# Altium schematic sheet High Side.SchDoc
size 431 x 279 mm; Date: Not shown in title block; ApprovedBy: Not shown in title block; CheckedBy: Not shown in title block; Author: Not shown in title block; CompanyName: Not shown in title block; Engineer: Not shown in title block; Organization: Not shown in title block; Address1: Not shown in title block; Address2: Not shown in title block; Address3: Not shown in title block; Address4: Not shown in title block; DocumentNumber: 4; Revision: Use project parameter SCH_Rev; SheetNumber: 4; SheetTotal: 5; PageSetup: Record=PageOptions¦CenterHorizontal=True¦CenterVertical=True¦PrintScale=1.00¦XCorrection=1.00¦YCorrection=1.00¦PrintKind=0¦BorderSize=5000000¦LeftOffset=0¦BottomOffset=0¦Orientation=2¦PaperLength=1000¦PaperWidth=1000¦Scale=100¦PaperSource=15¦PrintQuality=600¦MediaType=1¦DitherType=10¦PaperKind=Letter¦PrintScaleMode=1
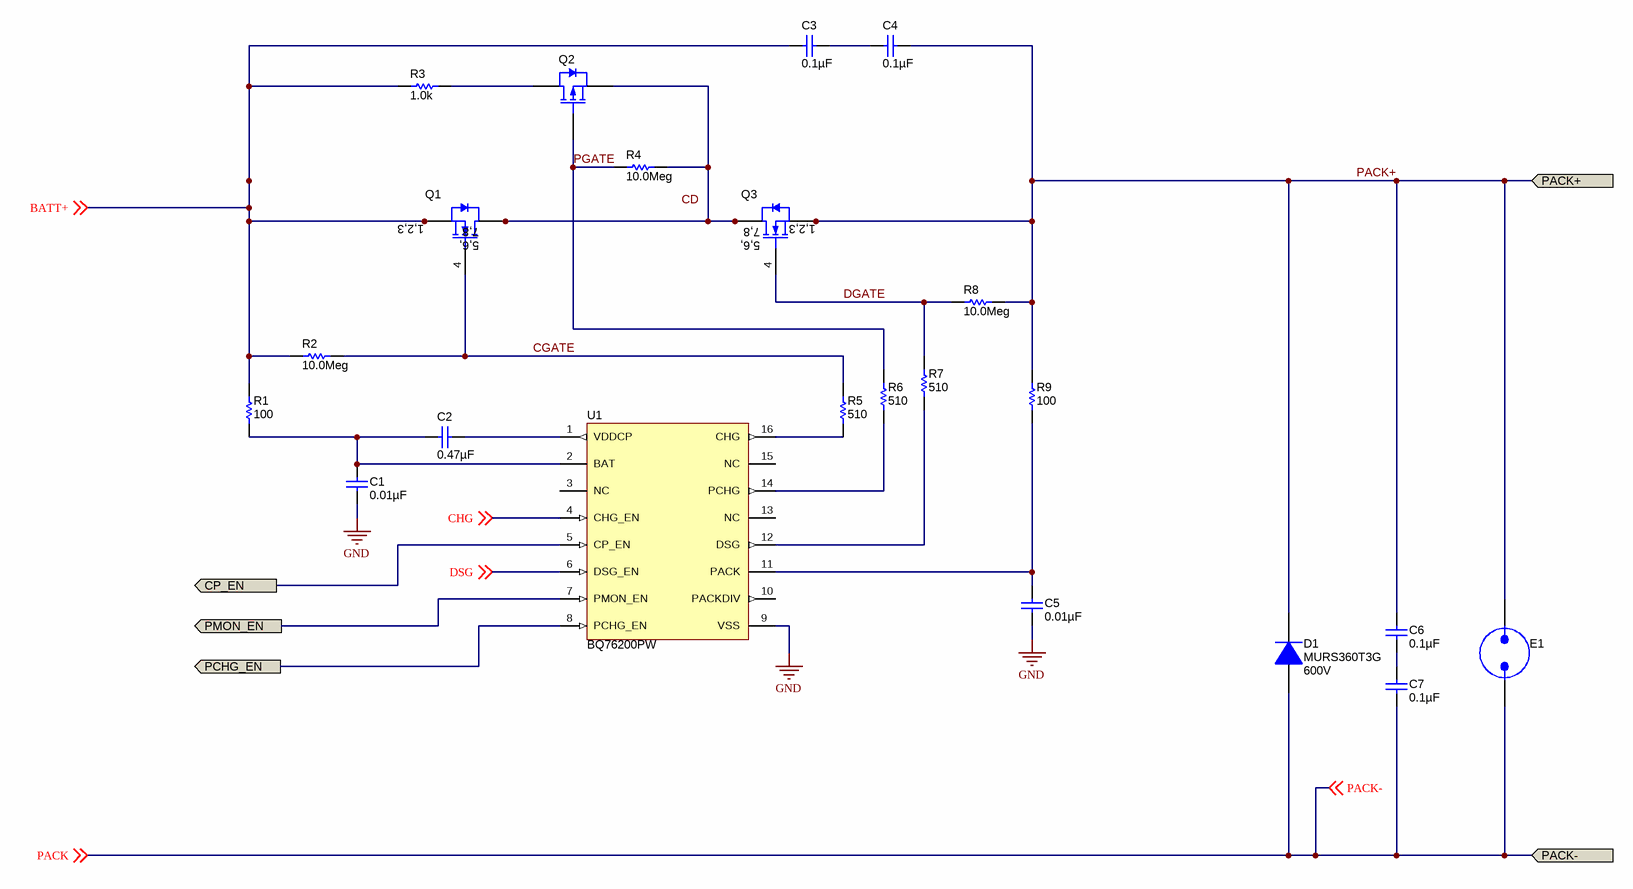
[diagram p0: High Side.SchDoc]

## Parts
C1  ValueDisplayed: 0.01µF  [0805_HV]  (hidden comment: 08051C103KAT2A)
C2  ValueDisplayed: 0.47µF  [0805_HV]  (hidden comment: C2012X7R1E474K)
C3  ValueDisplayed: 0.1µF  [0603]  (hidden comment: GRM188R72A104KA35D)
C4  ValueDisplayed: 0.1µF  [0603]  (hidden comment: GRM188R72A104KA35D)
C5  ValueDisplayed: 0.01µF  [0805_HV]  (hidden comment: 08051C103KAT2A)
C6  ValueDisplayed: 0.1µF  [0603]  (hidden comment: GRM188R72A104KA35D)
C7  ValueDisplayed: 0.1µF  [0603]  (hidden comment: GRM188R72A104KA35D)
D1  MURS360T3G  value 600V  [SMC]
E1  N/A  [SPARK_GAP2]  (value not drawn)  (no BOM)
Q1  CSD19531Q5A  [TRANS_NexFET_Q5A]  (value not drawn)
Q2  ZXMP10A13FTA  [SOT-23]  (value not drawn)
Q3  CSD19531Q5A  [TRANS_NexFET_Q5A]  (value not drawn)
R1  value 100  [0603]  (hidden comment: CRCW0603100RFKEA)
R2  value 10.0Meg  [0603]  (hidden comment: CRCW060310M0FKEA)
R3  value 1.0k  [2512M]  (hidden comment: ERJ-1TYJ102U)
R4  value 10.0Meg  [0603]  (hidden comment: CRCW060310M0FKEA)
R5  ValueDisplayed: 510  [0603]  (hidden comment: CRCW0603510RJNEA)
R6  ValueDisplayed: 510  [0603]  (hidden comment: CRCW0603510RJNEA)
R7  ValueDisplayed: 510  [0603]  (hidden comment: CRCW0603510RJNEA)
R8  value 10.0Meg  [0603]  (hidden comment: CRCW060310M0FKEA)
R9  value 100  [0603]  (hidden comment: CRCW0603100RFKEA)
U1  BQ76200PW  [PW0016A_N]

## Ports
CP_EN, PACK+, PACK-, PCHG_EN, PMON_EN

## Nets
GND: C1.2 C5.2 U1.9(VSS)
BATT+: C3.2 Q1.1(S) Q1.2(S) Q1.3(S) R1.2 R2.1 R3.1 ; off-sheet BATT+
CGATE: Q1.4(G) R2.2 R5.1
CHG: U1.4(CHG_EN) ; off-sheet CHG
CP_EN: U1.5(CP_EN) ; port CP_EN
DGATE: Q3.4(G) R7.1 R8.1
DSG: U1.6(DSG_EN) ; off-sheet DSG
PACK: C7.1 D1.2(A) E1.1 ; off-sheet PACK-, off-sheet PACK, port PACK-  [also labelled PACK-]
PACK+: C4.1 C6.2 D1.1(K) E1.2 Q3.1(S) Q3.2(S) Q3.3(S) R8.2 R9.2 ; port PACK+
PCHG_EN: U1.8(PCHG_EN) ; port PCHG_EN
PGATE: Q2.1(G) R4.1 R6.1
PMON_EN: U1.7(PMON_EN) ; port PMON_EN
NetC1_1: C1.1 C2.2 R1.1 U1.2(BAT)
NetC2_1: C2.1 U1.1(VDDCP)
NetC3_1: C3.1 C4.2
NetC5_1: C5.1 R9.1 U1.11(PACK)
NetC6_1: C6.1 C7.2
NetQ1_5: Q1.5(D) Q1.6(D) Q1.7(D) Q1.8(D) Q1.9(D) Q2.2(S) Q3.5(D) Q3.6(D) Q3.7(D) Q3.8(D) Q3.9(D) R4.2
NetQ2_3: Q2.3(D) R3.2
NetR5_2: R5.2 U1.16(CHG)
NetR6_2: R6.2 U1.14(PCHG)
NetR7_2: R7.2 U1.12(DSG)

Not connected (* = marked no-connect by the designer): U1 3(NC) 10(PACKDIV) 13(NC) 15(NC)

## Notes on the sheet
- Labels drawn without touching a wire or pin: CD

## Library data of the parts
C1 C5 = 08051C103KAT2A: CAP, CERM, 0.01uF, 100V, +/-10%, X7R, 0805; Manufacturer: AVX; Polarized: N; CompType: Capacitor; U/M: EA; Cap_F: 0.00000001; Tolerance_%: 10; ESR_Ohm: 0.078; Value1: 0.078 ohm; VDC_V: 100; TaMin_C: -55; TaMax_C: 125; Cap_Case: 0805
C2 = C2012X7R1E474K: CAP, CERM, 0.47uF, 25V, +/-10%, X7R, 0805; Manufacturer: TDK; Polarized: N; CompType: Capacitor; U/M: EA; Cap_F: 0.00000047; Tolerance_%: 10; ESR_Ohm: 0.0101; Value1: 0.0101 ohm; VDC_V: 25; TaMin_C: -55; TaMax_C: 125; Cap_Case: 0805
C3 C4 C6 C7 = GRM188R72A104KA35D: CAP, CERM, 0.1uF, 100V, +/-10%, X7R, 0603; Manufacturer: MuRata; Polarized: N; CompType: Capacitor; U/M: EA; Cap_F: 0.0000001; Tolerance_%: 10; Value1: Unknown; VDC_V: 100; TaMin_C: -55; TaMax_C: 125
D1 = MURS360T3G: Diode, Ultrafast, 600V, 3A, SMC; Manufacturer: ON Semiconductor; U/M: EA; Vf_V: 1.25; Io_A: 3; Vr_V: 600; Value2: 1.25V; TJmax_C: 175; RJC_CperW: 11
E1 = SparkGap: Spark Gap; SymbolCreator: a0412235
Q1 Q3 = CSD19531Q5A: MOSFET, N-CH, 100V, 16A, SON 5x6mm; Manufacturer: Texas Instruments; Alternate Manufacturer: None; U/M: EA; ChType: N; VdsMax_V: 100; Value1: ? ohm; Value2: 36 nC; QgTyp_nC: 36; Vgs_V: 20; IdsMax_A: 16
Q2 = ZXMP10A13FTA: MOSFET, P-CH, -100V, -0.6A, SOT-23; Manufacturer: Diodes Inc.; Alternate Manufacturer: None; U/M: EA; ChType: P; VdsMax_V: -100; Value1: 1 ohm; Rdson45_Ohm: 1; Value2: 3.5 nC; QgTyp_nC: 3.5; Vgs_V: -4; IdsMax_A: -0.6
R1 R9 = CRCW0603100RFKEA: RES, 100 ohm, 1%, 0.1W, 0603; Manufacturer: Vishay-Dale; CompType: Resistor; Value_Code: 100R; Tolerance_%: 1; Power_W: 0.1; VDC_V: 75; TempCo: 100 ppm/C; EIA_Code: E96; U/M: EA
R2 R4 R8 = CRCW060310M0FKEA: RES, 10.0Meg ohm, 1%, 0.1W, 0603; Manufacturer: Vishay-Dale; CompType: Resistor; Res_ohm: 10000000; Value_Code: 10M0; Tolerance_%: 1; Power_W: 0.1; VDC_V: 75; TempCo: 100 ppm/C; EIA_Code: E96; U/M: EA
R3 = ERJ-1TYJ102U: RES, 1.0k ohm, 5%, 1W, 2512; Manufacturer: Panasonic; CompType: Resistor; Res_ohm: 1000; Value_Code: 1k00; Tolerance_%: 5; Power_W: 1; VDC_V: 200; TempCo: 200 ppm/C; EIA_Code: E24; U/M: EA
R5-R7 = CRCW0603510RJNEA: RES, 510, 5%, 0.1 W, 0603; Manufacturer: Vishay-Dale; CompType: Resistor; Value: 510; Value_Code: 510R; Tolerance_%: 5; Power_W: 0.1; Value2: 0.1W; VDC_V: 75; TempCo: 200 ppm/C; SizeArea_mm2: 1.28; SizeX_mm: 1.6; SizeY_mm: 0.8; SizeZ_mm: 1; EIA_Code: E24; U/M: EA; AEC Category: Q200
U1 = BQ76200PW: bq76200: Low-Power, High-Side N-channel FET Driver with Pack Voltage Monitor, PW0016A; Alternate Manufacturer: None; Manufacturer: Texas Instruments; SymbolCreator: x0208325; CompType: IC; U/M: EA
